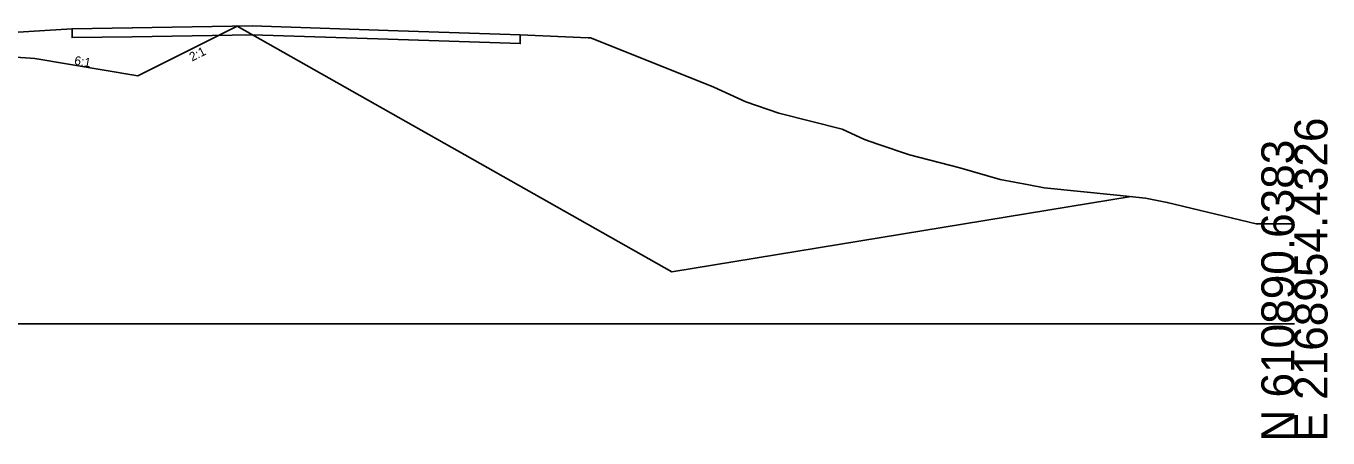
# Model space of a CAD drawing. Extents: x -26 to 1303, y -3010 to 12033.
# Drawn here: x 1192.6 to 1302.8, y 9490.3 to 9525.2 of the extents above; entities that cross this region are included whole.
import ezdxf

# ---------------------------------------------------------------- set-up
doc = ezdxf.new("R2010")
doc.units = 0
for name, color, linetype in [('RD_GPK_XS_Cell', 7, 'Continuous'), ('RD_Sketch10', 7, 'Continuous'), ('RD_XS_ExGround', 7, 'Continuous'), ('RD_XS_ExPaveRet', 7, 'Continuous'), ('RD_XS_Greenside', 7, 'Continuous'), ('RD_XS_TieSlope', 7, 'Continuous'), ('RD_XS_TX_Slope', 7, 'Continuous')]:
    doc.layers.add(name, color=color, linetype=linetype)

msp = doc.modelspace()

# ---------------------------------------------------------------- linework, layer by layer
at = {"layer": 'RD_GPK_XS_Cell'}
msp.add_line((1150, 9500), (1300, 9500), dxfattribs=at)
at = {"layer": 'RD_Sketch10'}
msp.add_lwpolyline([(1210.44, 9525.23), (1247.27, 9504.39), (1286.17, 9510.78)], dxfattribs=at)
at = {"layer": 'RD_XS_ExGround'}
msp.add_lwpolyline([(1189.16, 9524.55), (1194.14, 9524.88), (1196.45, 9525.02), (1201.55, 9525.09), (1211.7, 9525.25), (1223.23, 9524.88), (1234.42, 9524.51), (1240.18, 9524.25), (1240.38, 9524.24), (1241.72, 9523.7), (1250.81, 9520.05), (1253.52, 9518.81), (1256.31, 9517.87), (1261.7, 9516.51), (1263.59, 9515.61), (1264.71, 9515.22), (1267.39, 9514.33), (1271.66, 9513.22), (1275.07, 9512.23), (1277.49, 9511.79), (1278.81, 9511.53), (1284.96, 9510.91), (1287.38, 9510.65), (1289.23, 9510.29), (1296.77, 9508.47), (1297.6, 9508.47), (1300, 9508.47)], dxfattribs=at)
at = {"layer": 'RD_XS_ExPaveRet'}
for points in [[(1234.42, 9524.51), (1234.42, 9523.76), (1234.42, 9523.76), (1234.42, 9523.76), (1223.23, 9524.13), (1223.23, 9524.13), (1211.7, 9524.5), (1211.7, 9524.5), (1211.7, 9524.5), (1201.55, 9524.34), (1201.55, 9524.34), (1196.45, 9524.27), (1196.45, 9525.02), (1196.45, 9525.02), (1201.55, 9525.09), (1201.55, 9525.09), (1211.7, 9525.25), (1211.7, 9525.25), (1211.7, 9525.25), (1223.23, 9524.88), (1223.23, 9524.88), (1234.42, 9524.51), (1234.42, 9524.51)], [(1234.42, 9524.51), (1223.23, 9524.88), (1211.7, 9525.25), (1201.55, 9525.09), (1196.45, 9525.02), (1196.45, 9524.27), (1201.55, 9524.34), (1211.7, 9524.5), (1223.23, 9524.13), (1234.42, 9523.76), (1234.42, 9523.76), (1234.42, 9524.51), (1234.42, 9524.51)]]:
    msp.add_lwpolyline(points, dxfattribs=at)
at = {"layer": 'RD_XS_Greenside'}
for p, q in [((1202.03, 9521.02), (1210.44, 9525.23)), ((1193.3, 9522.48), (1202.03, 9521.02))]:
    msp.add_line(p, q, dxfattribs=at)
at = {"layer": 'RD_XS_TieSlope'}
msp.add_line((1191.3, 9522.64), (1193.3, 9522.48), dxfattribs=at)

# ---------------------------------------------------------------- texts
at = {"layer": 'RD_GPK_XS_Cell'}
for s, p in [('E 2168954.4326', (1302.8, 9490)), ('N 610890.6383', (1300, 9490))]:
    msp.add_text(s, height=2.8, rotation=90, dxfattribs=at).set_placement(p)
at = {"layer": 'RD_XS_TX_Slope'}
for s, rotation, p in [('6:1', 350.5377, (1196.6, 9521.98)), ('2:1', 26.5651, (1206.61, 9522.23))]:
    msp.add_text(s, height=0.75, rotation=rotation, dxfattribs=at).set_placement(p)

doc.saveas('drawing.dxf')
